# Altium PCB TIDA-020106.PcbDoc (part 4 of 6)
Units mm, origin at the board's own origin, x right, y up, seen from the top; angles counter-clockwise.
Board outline 158.53 x 83.25 mm, 6 copper layers (Top Layer, GND, Power, Sig4, GND (Mid4), Bottom Layer), stack 1.59 mm thick; 410 components, 255 nets, 1280 pads, 2405 vias.
Unrouted connection lines stored in the file: 294.
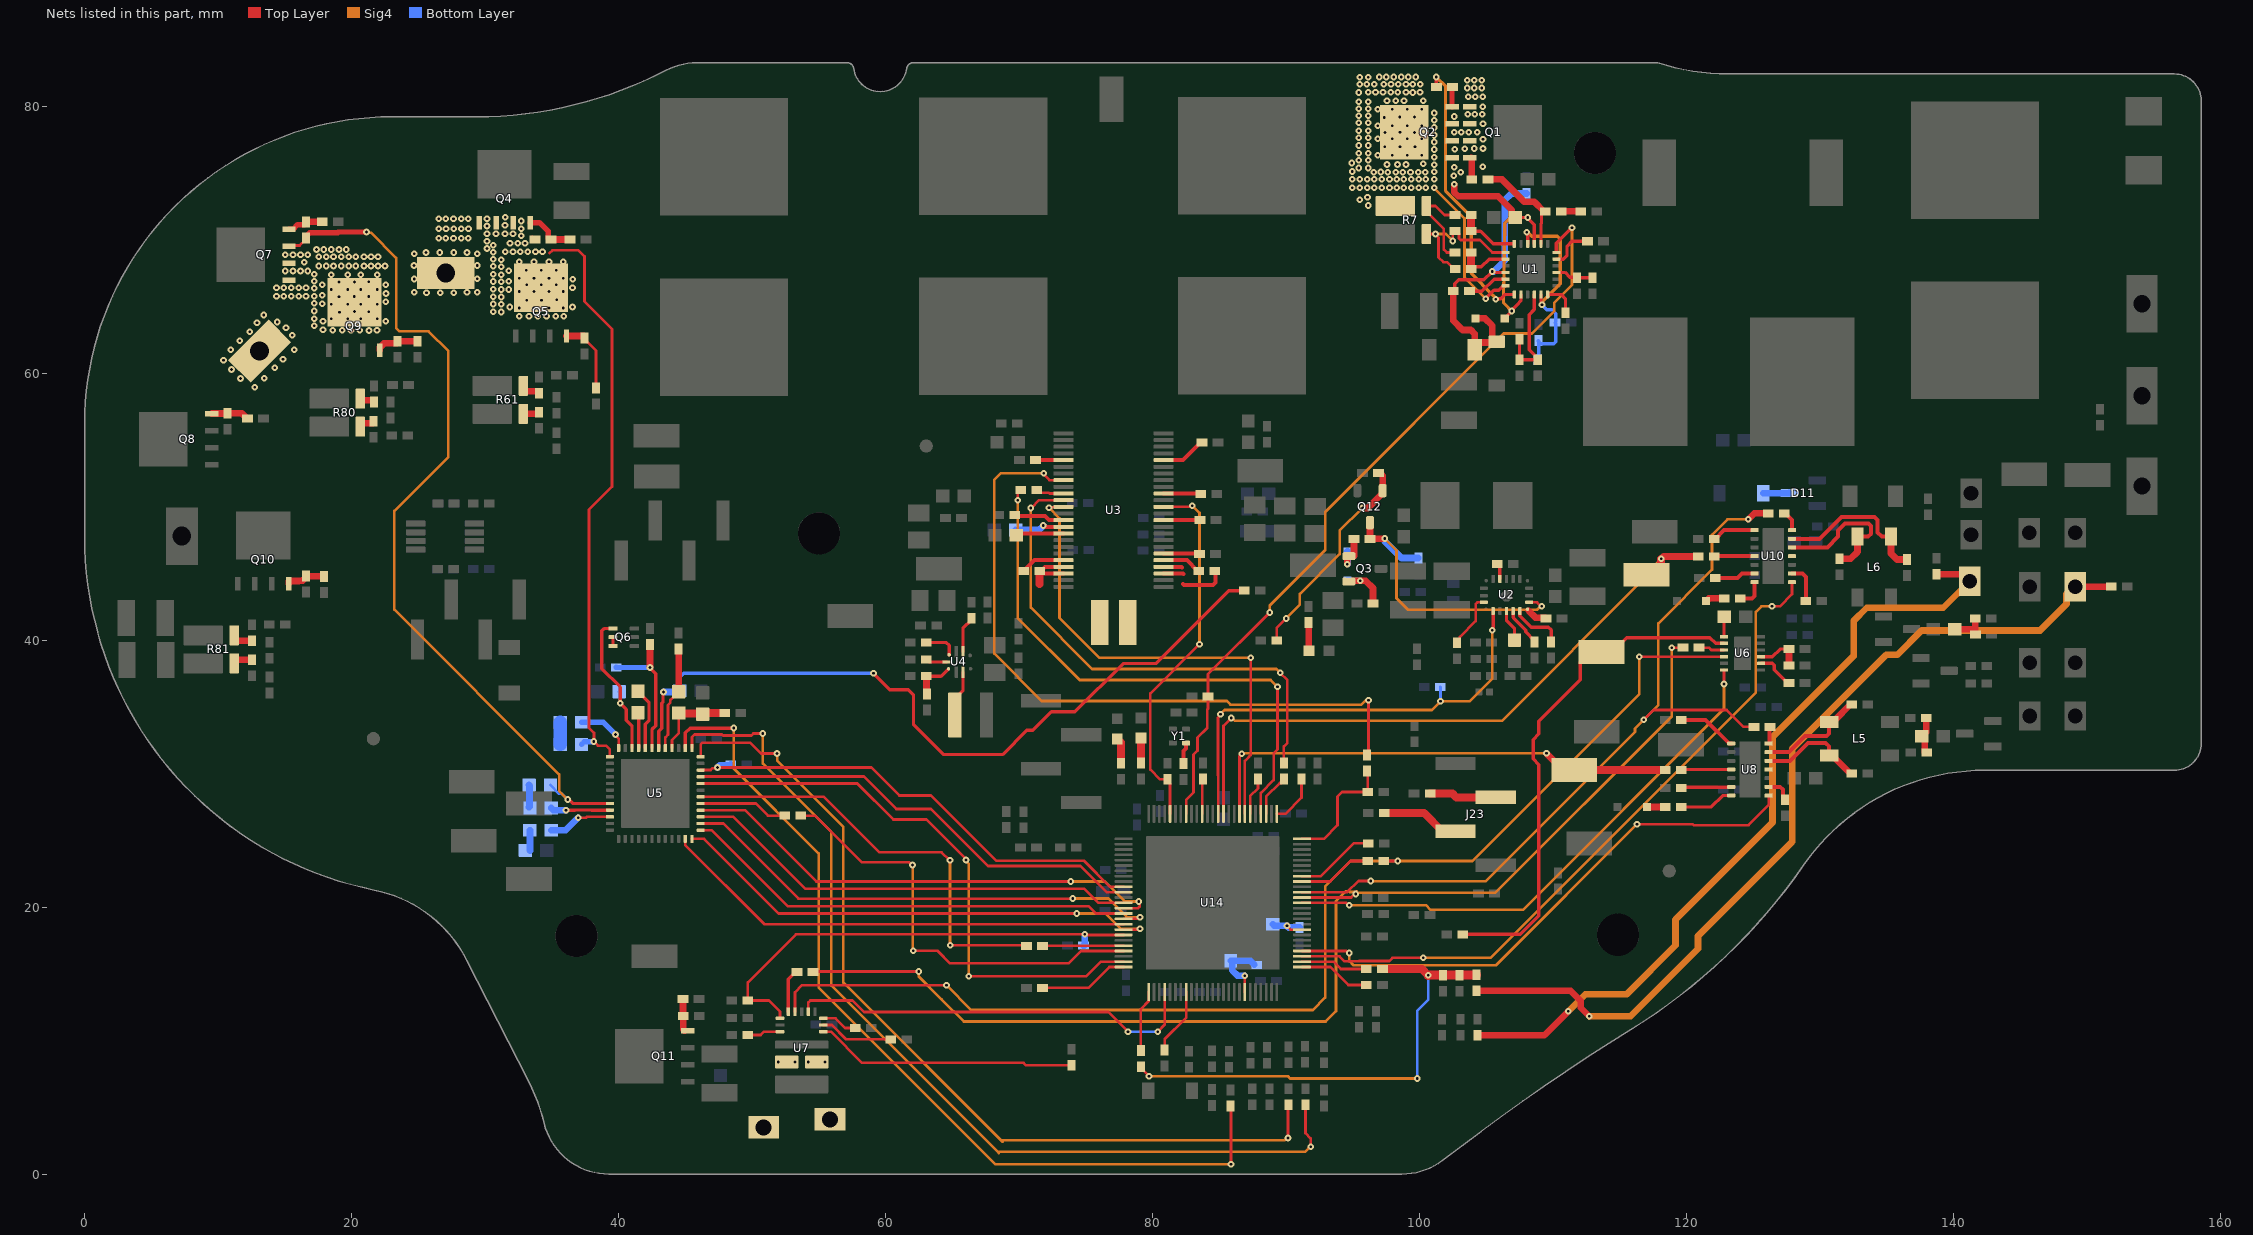
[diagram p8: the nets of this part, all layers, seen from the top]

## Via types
v1: diameter 0.5, hole 0.2, Top Layer to Bottom Layer, 2315 vias
v2: diameter 0.5, hole 0.2, Top Layer to Bottom Layer, tented both sides, 87 vias
v3: diameter 0.6, hole 0.2, Top Layer to Bottom Layer, 3 vias

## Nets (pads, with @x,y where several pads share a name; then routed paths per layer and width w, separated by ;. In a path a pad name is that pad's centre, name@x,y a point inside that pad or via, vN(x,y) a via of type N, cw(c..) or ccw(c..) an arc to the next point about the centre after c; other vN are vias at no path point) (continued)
nCS_DRV3263: U5.20 U14.99 | length 43.2
  Top Layer w0.2: U5.20@46.143,29.265 57.87,29.265 60.57,26.565 63.053,26.565 66.013,23.605 v1(66.013,23.532) ; v1(66.23,14.811) 75.013,14.811 76.119,15.917 U14.99@77.827,15.917
  Sig4 w0.2: v1(66.013,23.532) 66.013,23.451 66.23,23.234 v1(66.23,14.811)
NetC7_2: C7.2 D2.2 Q1.1 Q1.2 Q1.3 Q2.1 Q2.2 Q2.3 U1.2 U1.15 | length 20.2
  Top Layer w0.25: D2.2@106.371,64.098 106.892,64.62 v1(106.892,64.648) 106.892,64.716 107.293,65.117 107.293,65.123 107.586,65.416 U1.2@107.586,65.889 ; C7.2@107.157,71.658 v1(108.094,71.658) ; v1@108.097,71.61 108.586,71.121 U1.15@108.586,69.689
  Top Layer w0.5: v1(102.591,74.135) 102.591,73.536 102.884,73.243 105.863,73.243 106.903,72.202 106.903,71.883 107.128,71.658 C7.2@107.153,71.658 C7.2@107.157,71.658
  Sig4 w0.25: v1(106.892,64.648) 106.345,65.214 106.275,65.287 106.275,65.39 106.38,71.227 106.811,71.658 v1(108.094,71.658)
  other v1: 102.559,74.785 103.072,75.036 102.591,75.412 104.711,75.464 102.625,76.78 103.367,76.799 104.091,76.819 104.741,76.819 104.739,77.521 102.592,78.041 103.112,78.041 103.67,78.041 104.316,78.041 104.739,78.676 102.591,79.219 103.601,79.383 104.122,79.383 104.679,79.383 104.711,79.959 103.633,80.696 104.154,80.696 104.711,80.696 103.562,81.355 104.083,81.355 104.64,81.355 103.562,81.942 104.083,81.942 104.64,81.942
NetC11_1: C11.1 U1.23 | length 3.1
  Top Layer w0.2: C11.1@103.723,66.135 C11.1@103.823,66.135
  Top Layer w0.25: C11.1@103.823,66.135 104.663,66.135 105.568,67.039 U1.23@106.436,67.039
NetC11_2: C11.2 C12.2 D2.1 D10.1 R153.2 U1.22 | length 22.4
  Top Layer w0.25: C11.2@102.523,66.135 102.634,66.246 102.634,66.685 102.931,66.981 104.796,66.981 105.422,67.608 v1(105.422,67.614) 105.49,67.614 105.565,67.539 U1.22@106.436,67.539
  Top Layer w0.5: C11.2@102.523,66.135 102.523,63.925 103.213,63.235 103.829,63.235 104.122,62.942 C12.2@104.122,61.991 ; C12.2@104.122,61.741 C12.2@104.122,61.991 ; D2.1@104.171,64.098 104.894,64.098 105.435,63.558 105.435,62.558 D10.1@105.642,62.351 ; D10.1@105.704,62.291 104.422,62.291 C12.2@104.122,61.991
  Bottom Layer w0.5: v1(105.422,67.614) 105.551,67.614 106.371,68.434 106.371,72.963 106.866,73.459 R153.2@108.013,73.459
NetC13_1: C13.1 R10.1 U1.18 | length 4.8
  Top Layer w0.25: C13.1@103.849,70.633 104.558,70.633 105.501,69.689 U1.18@107.086,69.689
  Top Layer w0.6: C13.1@103.849,70.633 R10.1@103.849,71.845
NetC13_2: C13.2 C14.2 R7.3 U1.19 | length 11.1
  Top Layer w0.2: R7.3@100.462,70.413 100.464,70.415 v1(101.187,70.415) 101.187,70.368 101.407,70.148 101.407,68.669 101.767,68.309 102.04,68.309 102.56,67.789 C14.2@102.66,67.789 ; v1(102.487,69.895) 102.487,70.433 102.687,70.633 102.749,70.633 102.949,70.433 102.949,70.086 103.066,69.969 104.512,69.969 105.443,69.039 U1.19@106.436,69.039
  Sig4 w0.2: v1(101.187,70.415) 101.967,70.415 v1(102.487,69.895)
NetC14_1: C14.1 R11.1 U1.20 | length 4.1
  Top Layer w0.25: C14.1@103.849,67.789 C14.1@103.86,67.789 104.035,67.964 104.624,67.964 105.199,68.539 U1.20@106.436,68.539
  Top Layer w0.6: C14.1@103.849,67.789 R11.1@103.849,69.039
NetC15_1: C15.1 R12.1 R14.2 U1.4 | length 8.2
  Top Layer w0.25: R12.1@107.48,62.536 R14.2@107.48,61.004 108.292,61.004 C15.1@108.842,61.004 108.842,61.104 108.205,61.741 108.205,64.384 108.586,64.765 108.586,65.364 U1.4@108.586,65.889
NetC18_1: C18.1 R16.1 | length 1.5
  Top Layer w0.5: R16.1@110.596,72.122 C18.1@112.056,72.122
NetC19_1: C19.1 R21.2 U1.9 | length 2.9
  Top Layer w0.25: U1.9@110.236,67.539 110.886,67.539 111.251,67.174 111.736,67.174 R21.2@111.771,67.139 112.943,67.139 C19.1@112.947,67.135
NetC20_1: C20.1 U2.15 | length 1.2
  Top Layer w0.25: C20.1@105.815,45.711 105.827,45.711 106.002,45.536 U2.15@106.002,44.581
NetC29_2: C29.2 U2.4 | length 2.4
  Top Layer w0.25: U2.4@106.502,42.181 106.502,41.463 107.102,40.863 C29.2@107.102,40.002
NetC38_1: C38.1 L3.2 U3.3 U3.4 | length 6
  Top Layer w0.3: U3.3@80.824,44.985 81.802,44.985 82.282,44.985 82.316,44.952 ; U3.4@80.824,45.485 82.158,45.485 82.196,45.447 ; 82.274,44.203 82.356,44.121 84.525,44.121 84.702,44.298 C38.1@84.702,44.895
NetC38_2: C38.2 U3.5 | length 3
  Top Layer w0.3: U3.5@80.824,45.985 82.564,45.985 83.358,45.191 C38.2@83.458,45.191
NetC39_1: C39.1 L3.1 U3.45 U3.46 | length 4.7
  Top Layer w0.3: C39.1@71.536,45.191 C39.1@71.636,45.191 ; U3.46@73.324,44.985 71.841,44.985 C39.1@71.636,45.191 ; U3.45@73.324,45.485 71.931,45.485 C39.1@71.636,45.191
  Top Layer w0.6: 71.536,44.206 C39.1@71.536,45.191
NetC39_2: C39.2 U3.44 | length 3.4
  Top Layer w0.3: C39.2@70.336,45.191 70.436,45.191 70.586,45.341 70.586,45.441 71.131,45.985 U3.44@73.324,45.985
NetC53_2: C53.2 U3.39 | length 3.8
  Top Layer w0.3: v1(71.8,48.584) 71.854,48.584 71.953,48.485 U3.39@73.324,48.485
  Bottom Layer w0.5: C53.2@69.743,48.243 71.488,48.243 71.8,48.554 v1(71.8,48.584)
NetC54_2: C54.2 U3.40 | length 3.3
  Top Layer w0.3: C54.2@70.03,47.956 70.058,47.984 71.882,47.984 71.883,47.985 72.08,47.985 U3.40@73.324,47.985
NetC59_2: C59.2 U4.8 | length 1.7
  Top Layer w0.25: C59.2@62.957,38.549 63.057,38.549 63.241,38.365 U4.8@64.586,38.365
NetC62_1: C62.1 R51.1 U5.30 | length 57.9
  Top Layer w0.25: U5.30@42.993,31.915 42.993,33.168 43.218,33.393 43.218,35.263 43.32,35.365 43.32,36.076 v1(43.36,36.115) ; v1(59.085,37.517) 60.311,36.291 61.692,36.291 62.08,35.903 62.08,33.707 64.358,31.428 68.753,31.428 70.561,33.236 71.021,33.236 72.414,34.63 74.169,34.63 77.783,38.244 80.246,38.244 85.707,43.706 R51.1@86.852,43.706
  Bottom Layer w0.25: C62.1@44.569,36.218 44.569,37.202 44.884,37.517 v1(59.085,37.517)
  Bottom Layer w0.5: v1(43.36,36.115) 44.466,36.115 C62.1@44.569,36.218
NetC63_1: C63.1 R53.2 U5.29 | length 7.8
  Top Layer w0.2: U5.29@43.493,31.915 43.493,32.714 43.694,32.915 43.694,35.138 43.874,35.318 43.874,35.523 C63.1@44.494,36.143
  Top Layer w0.5: C63.1@44.494,36.143 R53.2@44.494,39.338
NetC63_2: C63.2 C64.2 R54.2 U5.28 | length 6.3
  Top Layer w0.2: U5.28@43.993,31.915 43.993,32.515 44.494,33.016 C63.2@44.494,34.543
  Top Layer w0.6: C63.2@44.494,34.543 44.539,34.498 46.248,34.498 C64.2@46.293,34.453 46.393,34.553 R54.2@47.888,34.553
NetC65_1: C65.1 U5.33 | length 2.7
  Top Layer w0.25: C65.1@41.443,34.57 41.493,34.52 U5.33@41.493,31.915
NetC65_2: C65.2 U5.32 | length 4.7
  Top Layer w0.25: C65.2@41.443,36.17 42.268,35.345 42.268,33.965 41.993,33.69 U5.32@41.993,31.915
NetC67_1: C67.1 Q6.4 U5.34 | length 11.5
  Top Layer w0.25: Q6.4@39.575,40.866 38.9,40.866 38.741,40.708 38.741,37.857 40.108,36.49 v1(40.108,35.268) 40.568,34.808 40.568,34.005 40.993,33.58 U5.34@40.993,31.915
  Bottom Layer w0.25: C67.1@40.033,36.143 40.108,36.068 v1(40.108,35.268)
NetC69_2: C69.2 R64.2 | length 1.7
  Bottom Layer w1: C69.2@35.619,32.186 R64.2@35.619,33.839
NetC72_2: C72.2 R65.2 | length 1.8
  Bottom Layer w0.2: R65.2@33.288,27.491 R65.2@33.352,27.427
  Bottom Layer w0.5: R65.2@33.288,27.491 33.32,27.523 33.32,29.113 C72.2@33.288,29.145
NetC77_2: C77.2 R68.2 | length 1.6
  Bottom Layer w0.5: R68.2@33.338,25.765 33.355,25.748 33.355,24.242 C77.2@33.372,24.225
NetC93_2: C93.2 R88.1 U6.3 | length 3.6
  Top Layer w0.25: U6.3@125.571,38.759 126.421,38.759 126.995,39.333 C93.2@127.655,39.333
  Top Layer w0.5: R88.1@127.659,38.105 C93.2@127.659,39.337
NetC95_1: C95.1 U6.7 | length 1.5
  Top Layer w0.25: U6.7@122.791,40.259 122.791,41.724 C95.1@122.816,41.749
NetC104_2: C104.2 R100.1 R103.2 | length 2.9
  Top Layer w0.5: R100.1@137.947,34.18 137.947,33.098 137.643,32.794 137.826,32.61 137.826,31.615 137.876,31.565 R103.2@137.976,31.565
NetC108_2: C108.2 R110.1 R113.2 | length 2.8
  Top Layer w0.5: C108.2@140.064,40.817 141.452,40.817 141.621,40.986 ; R110.1@141.618,41.634 141.621,41.63 141.621,40.986 ; R113.2@141.625,40.436 141.621,40.44 141.621,40.986
NetC116_1: C116.1 L7.2 U14.19 | length 5
  Top Layer w0.2: U14.19@86.902,13.642 v1(86.902,14.867)
  Bottom Layer w0.5: v1(86.902,14.867) 86.356,14.867 85.957,15.266 85.957,15.876 C116.1@85.843,15.989 87.309,15.989 L7.2@87.618,15.681
NetC117_1: C117.1 L8.2 U14.33 | length 3.4
  Top Layer w0.2: v1(90.057,18.595) 90.057,18.573 90.313,18.317 U14.33@91.177,18.317
  Bottom Layer w0.5: C117.1@88.989,18.723 89.116,18.595 v1(90.057,18.595) 90.18,18.473 L8.2@91.003,18.473
NetD3_1: D3.1 D11.3 | length 2
  Bottom Layer w0.5: D3.1@125.729,50.999 125.737,51.007 127.674,51.007 D11.3@127.681,51.014
NetD4_1: D4.1 R24.1 | length 2.1
  Top Layer w0.5: R24.1@91.665,41.317 91.684,41.298 91.684,39.221 D4.1@91.703,39.202
NetD6_2: D6.2 R102.2 | length 1.4
  Top Layer w0.5: D6.2@117.016,27.5 R102.2@118.393,27.5
NetD7_2: D7.2 R112.2 | length 1.4
  Top Layer w0.5: D7.2@121.454,42.922 121.66,43.127 R112.2@122.803,43.127
NetD8_2: D8.2 R151.1 | length 1.9
  Top Layer w0.6: D8.2@77.348,32.6 77.631,32.317 R151.1@77.631,30.773
NetD9_2: D9.2 R152.1 | length 1.9
  Top Layer w0.6: R152.1@79.123,30.793 D9.2@79.123,32.668
NetD13_1: D13.1 Q3.1 R28.1 | length 3
  Top Layer w0.5: v1(94.584,45.677) 94.584,46.241 94.634,46.291 Q3.1@94.699,46.291 ; Q3.1@95.026,46.255 95.076,46.305 R28.1@95.076,47.591
  Bottom Layer w0.5: v1(94.584,45.677) 94.589,45.681 D13.1@94.589,46.649
NetD13_2: D13.2 Q3.2 R23.2 | length 4
  Top Layer w0.5: Q3.2@94.875,44.366 94.949,44.441 95.53,44.441 v1(95.538,44.449) 95.949,44.449 96.5,43.898 R23.2@96.5,42.73
  Bottom Layer w0.5: D13.2@94.589,44.449 v1(95.538,44.449)
NetJ23_2: J23.2 R138.2 | length 5.9
  Top Layer w0.2: J23.2@101.927,25.68 J23.2@102.694,25.68
  Top Layer w0.6: R138.2@97.35,27.039 100.335,27.039 101.694,25.68 J23.2@101.927,25.68
NetJ23_3: J23.3 R139.2 | length 5
  Top Layer w0.6: R139.2@100.779,28.513 102.446,28.513 102.739,28.22 J23.3@105.694,28.22
NetL4_1: L4.1 U4.2 | length 3.5
  Top Layer w0.25: L4.1@65.176,34.394 65.176,35.604 65.786,36.214 U4.2@65.786,37.603
NetL5_3: L5.3 R98.2 U8.13 | length 8.2
  Top Layer w0.3: U8.13@126.136,31.608 127.677,31.608 128.877,32.808 130.472,32.808 130.676,33.012 L5.3@130.676,33.865
  Top Layer w0.5: L5.3@130.676,33.865 130.876,34.065 131.147,34.065 132.251,35.17 R98.2@132.351,35.17
NetL5_4: L5.4 R105.2 U8.12 | length 8.1
  Top Layer w0.3: U8.12@126.136,30.958 127.734,30.958 129.084,32.308 130.408,32.308 130.676,32.04 L5.4@130.676,31.365
  Top Layer w0.5: L5.4@130.676,31.365 130.901,31.365 132.201,30.065 132.201,30.047 132.251,29.997 R105.2@132.351,29.997
NetL6_3: L6.3 R109.2 U10.13 | length 11.9
  Top Layer w0.3: U10.13@127.889,47.59 129.959,47.59 131.598,49.228 134.051,49.228 134.3,48.98 134.3,48.071 134.627,47.743 L6.3@135.301,47.743
  Top Layer w0.5: L6.3@135.301,47.743 135.301,46.49 135.751,46.04 R109.2@136.492,46.04
NetL6_4: L6.4 R115.2 U10.12 | length 11.4
  Top Layer w0.3: U10.12@127.889,46.94 130.54,46.94 131.343,47.743 131.343,48.217 131.854,48.728 133.624,48.728 133.8,48.553 133.8,47.967 133.576,47.743 L6.4@132.801,47.743
  Top Layer w0.5: R115.2@131.455,46.092 132.275,46.092 132.793,46.611 132.793,47.736 L6.4@132.801,47.743
NetQ1_4: Q1.4 R9.2 | length 1.7
  Top Layer w0.5: Q1.4@103.849,76.136 103.865,76.136 103.91,76.091 R9.2@103.91,74.515
NetQ2_4: Q2.4 R8.2 | length 1.4
  Top Layer w0.4: R8.2@102.422,81.3 102.422,79.951 102.427,79.946 Q2.4@102.451,79.946
NetQ2_5: Q2.5 R7.2 U1.24 | length 11.8
  Top Layer w0.25: v1(104.95,65.566) 104.95,65.592 105.562,66.205 105.927,66.205 106.261,66.539 U1.24@106.436,66.539
  Sig4 w0.2: v1(101.078,73.875) 103.359,71.594 103.359,67.157 v1(104.95,65.566)
  other v1: 96.135,72.552 95.508,72.98 96.091,73.166 94.956,73.875 95.508,73.875 96.073,73.875 96.594,73.875 97.151,73.875 97.734,73.875 98.291,73.875 98.811,73.875 99.376,73.875 99.928,73.875 100.463,73.875 94.956,74.515 95.508,74.515 96.073,74.515 96.594,74.515 97.151,74.515 97.734,74.515 98.291,74.515 98.811,74.515 99.376,74.515 99.928,74.515 100.463,74.515 101.078,74.515 96.549,75.055 97.079,75.058 97.602,75.055 98.206,75.055 98.737,75.055 99.312,75.055 99.881,75.055 100.421,75.055 94.956,75.096 101.078,75.091 95.44,75.359 96.14,75.359 101.078,75.612 97.556,75.621 98.336,75.621 98.967,75.621 100.275,75.687 94.907,75.738 95.44,75.938 96.14,75.938 101.078,76.169 96.861,76.314 97.939,76.314 99.056,76.314 100.161,76.314 95.44,76.478 96.14,76.478 101.078,76.753 97.385,76.954 98.529,76.954 99.642,76.954 95.44,77.047 96.14,77.047 101.078,77.31 96.861,77.551 97.939,77.551 99.056,77.551 100.161,77.551 95.44,77.622 96.14,77.622 101.078,77.83 97.403,78.022 99.608,78.022 98.529,78.041 95.44,78.153 96.14,78.153 101.078,78.395 96.861,78.535 97.939,78.535 99.056,78.535 100.161,78.535 95.44,78.757 96.14,78.757 101.078,78.948 97.35,79.15 98.503,79.188 99.608,79.188 95.442,79.28 96.142,79.28 101.078,79.482 96.861,79.771 97.939,79.771 99.056,79.771 100.161,79.771 95.44,79.809 96.14,79.809 95.44,80.336 96.14,80.336 97.556,80.397 98.206,80.406 98.825,80.397 100.275,80.397 95.442,81.024 96.148,81.027 96.688,81.027 97.256,81.027 97.832,81.027 98.363,81.027 98.967,81.027 99.49,81.024 100.019,81.027 95.508,81.626 96.029,81.626 96.586,81.626 97.316,81.626 97.85,81.626 98.403,81.626 98.967,81.626 99.488,81.626 100.045,81.626 95.508,82.158 96.148,82.158 96.963,82.181 97.498,82.181 98.05,82.181 98.615,82.181 99.135,82.181 99.693,82.181
NetQ4_4: Q4.4 R50.1 R52.2 | length 3.8
  Top Layer w0.4: Q4.4@33.362,71.273 34.074,71.273 34.73,70.617 34.73,70.111 34.83,70.011 R52.2@34.93,70.011
  Top Layer w0.5: R52.2@34.93,70.011 R50.1@36.356,70.011
NetQ5_4: Q5.4 R55.1 R56.2 | length 5.6
  Top Layer w0.2: R56.2@37.441,62.627 37.441,62.527 37.641,62.327 37.665,62.327 38.299,61.694 R55.1@38.299,58.884
  Top Layer w0.5: Q5.4@36.092,62.777 37.391,62.777 37.441,62.727 R56.2@37.441,62.627
NetQ6_5: Q6.5 Q6.6 | length 0.7
  Top Layer w0.2: Q6.6@39.575,39.566 Q6.5@39.575,40.216
NetQ7_4: Q7.4 R66.1 R69.2 | length 2.8
  Top Layer w0.2: R66.1@17.776,71.317 R66.1@17.797,71.338
  Top Layer w0.4: Q7.4@15.308,70.763 15.603,70.763 15.956,71.117 16.466,71.117 16.566,71.217 R69.2@16.566,71.317
  Top Layer w0.5: R69.2@16.566,71.317 16.576,71.327 17.766,71.327 R66.1@17.776,71.317
NetQ8_4: Q8.4 R67.1 R70.2 | length 2.9
  Top Layer w0.5: Q8.4@9.511,56.952 9.535,56.976 10.676,56.976 R70.2@10.7,57 11.75,57 12.05,56.7 12.05,56.644 12.1,56.594 R67.1@12.2,56.594
NetQ9_4: Q9.4 R72.1 R74.2 | length 3.3
  Top Layer w0.2: R72.1@24.941,62.38 R72.1@24.942,62.381
  Top Layer w0.5: Q9.4@22.109,61.713 22.109,61.918 22.421,62.23 23.383,62.23 23.433,62.28 R74.2@23.433,62.38 ; R74.2@23.433,62.38 R72.1@24.941,62.381
NetQ10_4: Q10.4 R73.1 R75.2 | length 3.1
  Top Layer w0.5: Q10.4@15.286,44.226 15.286,44.386 15.331,44.431 16.053,44.431 16.08,44.458 16.316,44.458 16.566,44.708 R75.2@16.566,44.808 16.585,44.788 17.92,44.788 R73.1@17.939,44.769
NetQ11_4: Q11.4 R85.2 R87.2 | length 2.8
  Top Layer w0.2: R87.2@44.791,11.884 R87.2@44.826,11.849 ; R85.2@44.791,13.122 R85.2@44.791,13.222 ; Q11.4@44.931,10.735 Q11.4@45.163,10.735
  Top Layer w0.5: R87.2@44.791,11.884 44.803,11.884 44.818,11.899 R85.2@44.818,13.122 ; R87.2@44.826,11.849 44.826,10.866 44.931,10.761 Q11.4@44.931,10.735
NetQ12_1: Q12.1 R154.1 R155.1 | length 16.3
  Top Layer w0.2: R154.1@89.303,39.955 89.303,40.93 v1(89.992,41.619)
  Top Layer w0.5: v1(95.711,49.901) 96.127,49.901 97.225,50.998 97.225,52.317 97.011,52.531 R155.1@96.911,52.531
  Sig4 w0.2: v1(89.992,41.619) 91.027,42.654 91.027,43.471 94.007,46.451 94.007,48.196 v1(95.711,49.901)
NetQ12_3: Q12.3 R27.2 R28.2 U2.8 | length 22.8
  Top Layer w0.2: U2.8@108.202,42.831 108.802,42.831 109.106,42.527 v1(109.136,42.527)
  Top Layer w0.5: R28.2@96.276,47.591 Q12.3@96.275,48.798 ; R28.2@96.276,47.591 97.354,47.591 v1(97.376,47.614)
  Sig4 w0.2: v1(97.376,47.614) 98.262,46.727 98.262,43.137 99.125,42.274 108.802,42.274 109.055,42.527 v1(109.136,42.527)
  Bottom Layer w0.5: v1(97.376,47.614) 97.376,47.413 98.633,46.155 R27.2@99.9,46.155
NetR7_4: R7.4 R10.2 R11.2 | length 7.2
  Top Layer w0.2: R11.2@102.649,69.039 102.03,69.039 101.807,69.261 101.807,70.809 100.501,72.115 R7.4@100.501,72.515 101.181,72.515 101.851,71.845 R10.2@102.649,71.845
NetR8_1: R8.1 U1.1 | length 20.8
  Top Layer w0.25: v1(101.246,82.179) 101.246,81.428 R8.1@101.253,81.421 ; v1(105.703,65.532) 105.749,65.577 106.086,65.577 106.398,65.889 U1.1@107.086,65.889
  Sig4 w0.25: v1(101.246,82.179) 101.936,81.489 101.936,73.638 103.849,71.725 103.849,67.597 103.849,67.493 105.525,65.804 v1(105.703,65.532)
NetR9_1: R9.1 R16.2 U1.14 | length 7.7
  Top Layer w0.25: U1.14@109.086,69.689 109.086,71.183 109.121,71.218 109.121,71.947 R16.2@109.296,72.122
  Top Layer w0.5: R9.1@105.11,74.515 106.163,74.515 107.85,72.829 108.589,72.829 R16.2@109.296,72.122
NetR19_2: R19.2 U1.6 | length 2.5
  Top Layer w0.25: U1.6@109.586,65.889 110.596,65.889 110.919,65.566 R19.2@110.919,64.512
NetR20_2: R20.2 U1.11 | length 3.3
  Top Layer w0.25: U1.11@110.236,68.539 110.746,68.539 111.036,68.829 111.036,69.514 111.4,69.877 R20.2@112.571,69.877
NetR25_1: R25.1 U2.20 | length 4.1
  Top Layer w0.2: R25.1@102.802,39.807 103.002,40.007 103.002,40.235 104.195,41.428 104.195,42.714 104.312,42.831 U2.20@104.802,42.831
NetR26_2: R26.2 U2.7 | length 1.6
  Top Layer w0.2: U2.7@108.071,42.312 U2.7@108.171,42.312
  Top Layer w0.5: 108.171,42.189 108.677,41.684 109.411,41.684 R26.2@109.461,41.634
NetR29_2: R29.2 U2.6 | length 4
  Top Layer w0.25: U2.6@107.502,42.181 107.502,41.826 108.367,40.961 109.642,40.961 109.842,40.762 R29.2@109.842,39.859
NetR30_1: R30.1 U2.5 | length 3
  Top Layer w0.25: U2.5@107.002,42.181 107.002,41.689 107.939,40.752 107.939,40.618 108.598,39.959 R30.1@108.598,39.859
NetR36_2: R36.2 U3.6 | length 2.7
  Top Layer w0.3: U3.6@80.824,46.485 83.465,46.485 R36.2@83.509,46.441
NetR37_2: R37.2 U3.38 | length 3.8
  Top Layer w0.3: R37.2@69.652,49.363 69.717,49.298 71.935,49.298 72.247,48.985 U3.38@73.324,48.985
NetR38_2: R38.2 U3.11 | length 2.7
  Top Layer w0.3: U3.11@80.824,48.985 83.527,48.985 R38.2@83.546,49.005
NetR39_2: R39.2 U3.15 | length 2.8
  Top Layer w0.3: U3.15@80.824,50.985 83.543,50.985 R39.2@83.593,50.935
NetR40_2: R40.2 U3.20 | length 3.4
  Top Layer w0.3: U3.20@80.824,53.485 82.259,53.485 83.592,54.818 R40.2@83.692,54.818
NetR41_2: R41.2 U3.29 | length 2.1
  Top Layer w0.3: R41.2@71.217,53.485 U3.29@73.324,53.485
NetR42_2: R42.2 U3.34 | length 2.1
  Top Layer w0.2: R42.2@71.312,51.24 71.512,51.04 72.212,51.04 72.267,50.985 U3.34@73.324,50.985
NetR43_1: R43.1 U3.32 | length 52.6
  Top Layer w0.2: v1(71.841,52.505) 71.899,52.448 71.899,52.36 72.274,51.985 U3.32@73.324,51.985 ; R43.1@96.069,31.393 96.163,31.488 v1(96.163,35.502)
  Sig4 w0.2: v1(71.841,52.505) 68.632,52.505 68.143,52.016 68.143,38.985 71.686,35.442 85.557,35.442 85.83,35.169 95.623,35.169 95.899,35.445 96.106,35.445 v1(96.163,35.502)
NetR45_1: R45.1 U4.5 | length 2.8
  Top Layer w0.25: U4.5@65.786,39.128 65.786,40.883 66.439,41.536 R45.1@66.439,41.636
NetR46_1: R46.1 R48.1 U4.9 | length 3.2
  Top Layer w0.25: R48.1@63.042,37.294 64.146,37.294 U4.9@64.707,37.856
  Top Layer w0.5: R48.1@63.042,37.294 63.06,37.277 63.06,35.977 R46.1@63.077,35.959
NetR49_2: R49.2 U4.7 | length 2.5
  Top Layer w0.25: R49.2@62.992,39.817 64.534,39.817 64.748,39.603 U4.7@64.748,38.903
NetR57_2: R57.2 R58.1 U5.31 | length 10.6
  Top Layer w0.25: v1(42.347,37.949) 42.347,37.906 42.768,37.486 42.768,33.58 42.493,33.305 U5.31@42.493,31.915
  Top Layer w0.5: R57.2@42.34,39.666 42.34,37.956 v1(42.347,37.949)
  Bottom Layer w0.4: R58.1@39.812,37.959 39.817,37.954 42.342,37.954 v1(42.347,37.949)
NetR59_2: R59.2 U5.17 | length 6.7
  Top Layer w0.2: U5.17@46.143,27.765 50.274,27.765 51.184,26.855 R59.2@52.435,26.855
NetR60_2: R60.2 R61.4 | length 1.7
  Top Layer w0.3: R61.4@32.911,59.052 R61.4@32.911,59.057
  Top Layer w0.5: R61.4@32.863,59.052 32.863,58.752 32.963,58.652 33.999,58.652 34.049,58.602 R60.2@34.049,58.502
NetR61_3: R61.3 R63.2 | length 1.3
  Top Layer w0.5: R61.3@32.863,56.952 33.985,56.952 34.035,57.002 R63.2@34.035,57.078
NetR64_1: R64.1 U5.36 | length 4
  Top Layer w0.2: v1(39.768,32.924) 39.768,32.843 39.993,32.617 U5.36@39.993,31.915
  Bottom Layer w0.4: R64.1@37.219,33.839 38.853,33.839 v1(39.768,32.924)
NetR65_1: R65.1 U5.45 | length 4.5
  Top Layer w0.25: v1(36.05,27.265) 36.724,27.265 36.734,27.275 37.985,27.275 37.995,27.265 U5.45@39.343,27.265
  Bottom Layer w0.5: R65.1@34.952,27.427 35.114,27.265 v1(36.05,27.265)
NetR68_1: R68.1 U5.46 | length 4.8
  Top Layer w0.2: v1(36.972,26.7) 37.557,26.7 37.622,26.765 U5.46@39.343,26.765
  Bottom Layer w0.5: R68.1@34.938,25.765 36.038,25.765 v1(36.972,26.7)
NetR71_2: R71.2 U5.26 | length 67.7
  Top Layer w0.2: R71.2@85.843,5.102 85.862,5.083 v1(85.862,0.75)
  Top Layer w0.25: U5.26@44.993,31.915 44.993,33.054 45.349,33.411 v1(48.618,33.411)
  Sig4 w0.2: v1(48.618,33.411) 48.618,30.39 54.979,24.029 54.979,13.972 68.201,0.75 v1(85.862,0.75)
NetR76_2: R76.2 U5.25 | length 71.9
  Top Layer w0.2: U5.25@45.493,31.915 45.493,32.732 45.696,32.935 47.743,32.935 47.817,32.861 49.941,32.861 50.085,33.004 v1(50.799,33.004) ; R76.2@91.445,5.191 91.445,3.065 91.827,2.683 v1(91.827,2.045)
  Sig4 w0.2: v1(50.799,33.004) 50.799,30.759 55.929,25.629 55.929,14.117 68.472,1.574 ; 68.472,1.674 91.42,1.674 91.791,2.045 v1(91.827,2.045)
NetR77_2: R77.2 U5.24 | length 67
  Top Layer w0.2: U5.24@46.143,31.265 46.143,32.165 46.293,32.315 49.844,32.315 50.654,31.504 v1(51.856,31.504) ; v1(90.14,2.7) 90.14,5.156 R77.2@90.175,5.191
  Sig4 w0.2: v1(51.856,31.504) 51.889,31.471 51.889,30.954 56.828,26.016 56.828,14.357 68.758,2.427 ; 68.758,2.527 89.885,2.527 90.059,2.7 v1(90.14,2.7)
NetR78_2: R78.2 R80.4 | length 1.3
  Top Layer w0.3: R80.4@20.483,58.053 20.483,58.038 R80.4@20.54,57.981
  Top Layer w0.5: R80.4@20.645,58.085 20.645,58.062 20.745,57.962 21.61,57.962 21.66,57.912 R78.2@21.66,57.838
NetR79_2: R79.2 R81.4 | length 1.7
  Top Layer w0.3: R81.4@11.26,40.36 R81.4@11.26,40.413
  Top Layer w0.5: R81.4@11.195,40.36 11.195,40.057 11.295,39.957 R79.2@12.522,39.957
NetR80_3: R80.3 R82.2 | length 1.3
  Top Layer w0.5: R80.3@20.645,55.985 20.645,56.148 20.745,56.248 21.579,56.248 21.629,56.298 R82.2@21.629,56.398
NetR81_3: R81.3 R83.2 | length 1.6
  Top Layer w0.5: R81.3@11.195,38.26 11.195,38.437 11.295,38.537 R83.2@12.534,38.537
NetR84_1: R84.1 TP16.1 U6.8 | length 38.6
  Top Layer w0.25: R84.1@103.227,17.963 107.542,17.963 108.928,19.35 108.928,30.681 108.505,31.104 108.505,32.553 108.928,32.976 108.928,33.929 112.028,37.029 112.028,38.345 112.792,39.109 TP16.1@113.617,39.109 114.443,39.109 115.521,40.187 121.738,40.187 122.166,39.759 U6.8@122.791,39.759
NetR86_1: R86.1 U6.2 | length 2.9
  Top Layer w0.25: U6.2@125.571,38.259 126.41,38.259 126.556,38.112 126.556,37.79 127.559,36.787 R86.1@127.659,36.787
NetR89_2: R89.2 U6.9 | length 1.9
  Top Layer w0.2: R89.2@120.916,39.433 121.664,39.433 121.838,39.259 U6.9@122.791,39.259
Netr90_2: R90.2 U7.8 | length 19.6
  Top Layer w0.2: U7.8@55.335,10.67 55.901,10.67 58.238,8.333 70.331,8.333 70.51,8.154 R90.2@73.919,8.154
NetR91_1: R91.1 U7.3 | length 2.5
  Top Layer w0.2: R91.1@49.669,10.425 50.635,10.425 50.88,10.67 U7.3@52.085,10.67
NetR93_2: R93.2 U7.9 | length 5.4
  Top Layer w0.2: U7.9@55.335,11.17 55.967,11.17 57.044,10.093 R93.2@60.29,10.093
NetR94_2: R94.2 U7.10 | length 2.7
  Top Layer w0.2: U7.10@55.335,11.67 56.239,11.67 56.962,10.947 R94.2@57.72,10.947
NetR96_2: R96.2 U7.15 | length 3.3
  Top Layer w0.25: U7.15@52.71,12.17 52.71,14.591 53.26,15.141 R96.2@53.36,15.141
NetR101_2: R101.2 U8.1 | length 4.5
  Top Layer w0.3: R101.2@119.593,34.029 121.416,34.029 123.186,32.258 U8.1@123.336,32.258
NetR102_1: R102.1 U8.7 | length 4.1
  Top Layer w0.25: R102.1@119.593,27.5 121.841,27.5 122.699,28.358 U8.7@123.336,28.358
NetR104_1: R104.1 U8.9 | length 2
  Top Layer w0.3: U8.9@126.136,29.008 127.006,29.008 127.206,28.808 127.206,28.189 R104.1@127.356,28.039
NetR106_2: R106.2 U8.14 | length 1.3
  Top Layer w0.3: U8.14@126.136,32.258 126.186,32.258 126.186,33.458 R106.2@126.237,33.508
NetR107_2: R107.2 U8.6 | length 3.8
  Top Layer w0.25: R107.2@119.593,28.908 119.668,28.983 123.311,28.983 U8.6@123.336,29.008
NetR108_2: R108.2 U8.4 | length 3.8
  Top Layer w0.25: R108.2@119.593,30.264 119.637,30.308 U8.4@123.336,30.308
NetR111_2: R111.2 U10.1 | length 3.4
  Top Layer w0.3: R111.2@122.054,47.591 122.154,47.591 122.803,48.24 U10.1@125.034,48.24 ; U10.1@125.084,48.24 U10.1@125.034,48.24 ; U10.1@125.089,48.24 U10.1@125.034,48.24
NetR112_1: R112.1 U10.7 | length 2.2
  Top Layer w0.3: R112.1@124.003,43.127 124.905,43.127 125.089,43.311 U10.7@125.089,44.34
NetR114_1: R114.1 U10.9 | length 2.9
  Top Layer w0.3: U10.9@127.884,44.99 U10.9@127.889,44.99 128.663,44.99 128.919,44.734 R114.1@128.919,42.941
NetR116_2: R116.2 U10.14 | length 1.6
  Top Layer w0.3: R116.2@127.302,49.501 127.402,49.501 127.889,49.014 U10.14@127.889,48.24
NetR117_2: R117.2 U10.6 | length 3.1
  Top Layer w0.3: R117.2@122.136,44.637 123.794,44.637 124.148,44.99 U10.6@125.089,44.99
NetR118_2: R118.2 U10.4 | length 3
  Top Layer w0.3: R118.2@122.073,46.264 122.099,46.29 U10.4@125.084,46.29
NetR128_1: R128.1 U14.26 | length 5.4
  Top Layer w0.2: U14.26@91.177,15.517 93.301,15.517 94.655,14.163 R128.1@96.008,14.163
NetR129_1: R129.1 U14.27 | length 5.1
  Top Layer w0.2: U14.27@91.177,15.917 93.542,15.917 94.092,15.367 R129.1@96.008,15.367
NetR133_2: R133.2 U14.42 | length 5.6
  Top Layer w0.2: U14.42@91.177,21.917 93.293,21.917 94.828,23.452 R133.2@96.115,23.452
NetR134_2: R134.2 U14.51 | length 3.7
  Top Layer w0.2: U14.51@89.302,26.992 89.937,26.992 91.144,28.199 R134.2@91.144,29.597
NetR135_2: R135.2 U14.43 | length 6
  Top Layer w0.2: U14.43@91.177,22.317 92.589,22.317 95.054,24.782 R135.2@96.15,24.782
NetR137_1: R137.1 Y1.3 | length 1.6
  Top Layer w0.3: R137.1@82.316,30.758 82.316,31.701 82.48,31.864 82.48,32.267 Y1.3@82.502,32.289
NetR140_1: R140.1 U14.53 | length 3.2
  Top Layer w0.2: U14.53@88.502,26.992 88.502,28.272 89.527,29.297 89.627,29.297 89.827,29.497 R140.1@89.827,29.597
NetR141_2: R141.2 U14.96 | length 6.1
  Top Layer w0.2: R141.2@71.749,16.988 71.878,17.117 U14.96@77.827,17.117
NetR142_1: R142.1 U14.56 | length 2.8
  Top Layer w0.2: U14.56@87.302,26.992 87.302,28.317 87.882,28.897 R142.1@87.882,29.597
NetR143_2: R143.2 U14.100 | length 6.7
  Top Layer w0.2: R143.2@71.749,13.958 75.197,13.958 76.756,15.517 U14.100@77.827,15.517
NetR144_1: R144.1 U14.1 | length 4.6
  Top Layer w0.2: R144.1@79.11,9.254 79.11,12.357 79.702,12.949 U14.1@79.702,13.642
NetR145_1: R145.1 U14.8 | length 5
  Top Layer w0.2: R145.1@80.902,9.295 80.902,10.105 82.502,11.705 U14.8@82.502,13.642
NetR146_1: R146.1 U14.65 | length 2.6
  Top Layer w0.2: U14.65@83.702,26.992 83.702,29.533 R146.1@83.771,29.602
NetU8_11: U8.11
NetU10_11: U10.11
nFAULT_CAN1: U8.8 U14.29 | length 41.5
  Top Layer w0.2: U14.29@91.177,16.717 94.522,16.717 94.672,16.567 v1(94.732,16.567) ; v1(116.277,26.217) 120.45,26.217 120.53,26.136 124.622,26.136 126.136,27.65 U8.8@126.136,28.358
  Sig4 w0.2: v1(94.732,16.567) 94.732,15.967 95.052,15.647 105.707,15.647 v1(116.277,26.217)
nFAULT_CAN2: U10.8 U14.28 | length 52.7
  Top Layer w0.2: U14.28@91.177,16.317 94.001,16.317 94.375,15.943 95.459,15.943 95.483,15.967 97.726,15.967 97.955,16.197 v1(100.254,16.197) ; v1(126.386,42.527) 126.973,42.527 127.889,43.442 U10.8@127.889,44.34
  Sig4 w0.2: v1(100.254,16.197) 105.297,16.197 125.181,36.081 125.181,42.122 125.586,42.527 v1(126.386,42.527)
nFAULT_EPB: C99.2 R92.2 U7.1 U14.94 | length 35.2
  Top Layer w0.2: U7.1@52.085,11.67 52.085,12.17 51.249,13.005 R92.2@49.669,13.005 49.669,14.362 53.27,17.963 v1(74.9,17.963) 74.946,17.917 U14.94@77.827,17.917
  Bottom Layer w0.5: C99.2@74.821,17.117 74.85,17.117 74.9,17.167 v1(74.9,17.963)
nFLT_DRV3263: R62.1 U5.22 U14.85 | length 36.9
  Top Layer w0.2: U5.22@46.143,30.265 46.885,30.265 47.026,30.406 47.258,30.406 47.336,30.485 v1@47.336,30.524 ; v1@47.299,30.562 v1@47.336,30.524 ; v1(47.396,30.464) v1@47.336,30.524 ; U14.85@77.827,21.517 76.799,21.517 74.834,23.482 68.272,23.482 63.389,28.365 61.024,28.365 58.925,30.464 47.472,30.464 47.394,30.542 47.336,30.599 v1@47.336,30.524
  Bottom Layer w0.5: v1(47.396,30.464) 47.564,30.632 48.354,30.632 R62.1@48.404,30.682
nFLT_LM74930: R15.1 U1.12 U14.68 | length 59.5
  Top Layer w0.2: U14.68@82.502,26.992 82.502,28.036 83.058,28.593 83.058,31.421 83.356,31.718 83.356,32.693 84.097,33.435 84.097,34.815 84.146,34.865 R15.1@84.146,35.77 84.146,37.449 v1(88.767,42.069)
  Top Layer w0.25: U1.12@110.236,69.039 110.236,69.729 v1(111.406,70.898)
  Sig4 w0.2: v1(88.767,42.069) 88.767,42.6 92.924,46.757 92.924,49.599 106.287,62.962 108.4,62.962 110.086,64.648 110.086,65.283 111.406,66.602 v1(111.406,70.898)
nSCS_EPB: U7.12 U14.4 | length 31.1
  Top Layer w0.2: U7.12@54.21,12.17 54.21,12.857 54.352,12.999 57.519,12.999 58.38,12.139 76.679,12.139 v1(78.148,10.67) ; v1(80.381,10.67) 80.902,11.191 U14.4@80.902,13.642
  Bottom Layer w0.2: v1(78.148,10.67) v1(80.381,10.67)
nSCS_PMIC: U3.36 U14.57 | length 37.1
  Top Layer w0.2: v1(72.227,49.918) 72.26,49.952 73.29,49.952 U3.36@73.324,49.985 ; U14.57@86.902,26.992 86.902,30.947 87.216,31.26 87.216,31.269 87.352,31.406 v1(87.352,38.671)
  Sig4 w0.2: v1(72.227,49.918) 73.024,49.12 73.024,41.665 76.019,38.671 v1(87.352,38.671)
nSCS_WSS: U6.12 U14.38 | length 41
  Top Layer w0.2: U14.38@91.177,20.317 94.481,20.317 94.651,20.148 v1(94.732,20.148) ; v1(122.791,36.718) U6.12@122.791,37.759
  Sig4 w0.2: v1(94.732,20.148) 100.474,20.148 100.825,19.797 107.729,19.797 122.791,34.859 v1(122.791,36.718)
nSLEEP_DRV3263: U5.21 U14.86 | length 35.3
  Top Layer w0.2: U5.21@46.143,29.765 46.166,29.789 58.367,29.789 60.801,27.355 63.398,27.355 67.671,23.082 74.586,23.082 76.551,21.117 U14.86@77.827,21.117
nSTB_CAN: R106.1 R116.1 U14.40 | length 61.1
  Top Layer w0.2: U14.40@91.177,21.117 94.57,21.117 95.412,21.96 v1(96.339,21.96) ; v1(116.778,34.029) 117.519,34.77 122.995,34.77 124.257,33.508 R106.1@125.037,33.508
  Top Layer w0.5: v1(124.61,49.043) 125.068,49.501 R116.1@126.102,49.501
  Sig4 w0.2: v1(96.339,21.96) 96.364,21.934 104.933,21.934 116.127,33.129 116.127,33.378 v1(116.778,34.029) 117.876,35.127 117.876,41.262 121.888,45.274 121.888,47.89 123.041,49.043 v1(124.61,49.043)
nXRS_DSP: C120.1 U3.13 U14.71 | length 27.9
  Top Layer w0.2: U3.13@80.824,49.985 82.82,49.985 82.893,50.059 v1(82.974,50.059) ; U14.71@81.302,26.992 81.302,29.265 81.1,29.467 C120.1@81.1,29.567 80.561,29.567 79.823,30.305 79.823,36.018 v1(83.502,39.698)
  Sig4 w0.2: v1(82.974,50.059) 83.502,49.531 v1(83.502,39.698)
OUTA_EPB: J5.1 U7.7
  other v2: 54.21,8.395 55.46,8.395
OUTB_EPB: J6.1 U7.5 | length 0.6
  Top Layer w0.2: v2(51.96,8.395) U7.5@52.585,8.395
  other v2: 53.21,8.395
OV: C17.1 R13.1 R17.2 U1.5 U1.16 | length 16.4
  Top Layer w0.25: v1(108.011,70.558) 108.011,70.49 108.086,70.415 U1.16@108.086,69.689 ; U1.5@109.086,65.889 109.086,65.254 109.161,65.179 v1(109.161,65.111)
  Sig4 w0.25: v1(108.011,70.558) 108.078,70.558 108.384,70.253 110.32,70.253 110.524,70.049 110.524,66.695 109.218,65.388 109.218,65.345 109.209,65.336 109.209,65.159 v1(109.161,65.111)
  Bottom Layer w0.25: C17.1@108.842,61.004 108.921,61.083 108.921,62.406 R13.1@108.886,62.441 108.886,62.371 109.061,62.196 110.048,62.196 110.197,62.345 110.197,63.719 R17.2@110.14,63.775 110.197,63.832 110.197,64.451 109.913,64.735 109.516,64.735 109.161,65.089 v1(109.161,65.111)
PEDAL_SENSOR_SENT: C2.1 R2.2 R4.2 R129.2 R144.2 | length 36.5
  Top Layer w0.2: R144.2@79.11,8.054 79.11,7.954 79.722,7.342 v1(79.722,7.334)
  Top Layer w0.6: R129.2@97.208,15.367 100.166,15.367 v1(100.63,14.903)
  Top Layer w0.7: v1(100.63,14.903) 100.646,14.919 104.24,14.919 R4.2@104.256,14.935
  Sig4 w0.2: v1(79.722,7.334) 90.115,7.334 90.286,7.163 v1(99.82,7.163)
  Bottom Layer w0.2: v1(99.82,7.163) 99.82,12.244 100.63,13.055 v1(100.63,14.903)
PFS: J12.1 R3.1 R5.2 | length 60.1
  Top Layer w0.5: R3.1@104.342,10.4 109.335,10.4 v1(111.138,12.203) ; R5.2@138.715,44.94 140.66,44.94 J12.1@141.2,44.4
  Sig4 w0.5: v1(111.138,12.203) 112.404,13.469 115.486,13.469 119.162,17.144 119.162,19.066 126.429,26.333 126.429,32.738 132.5,38.809 132.5,41.431 133.49,42.421 139.221,42.421 J12.1@141.2,44.4
PG_LM68645: R31.2 U2.2 U14.62 | length 35.2
  Top Layer w0.2: U14.62@84.902,26.992 84.902,29.883 84.897,29.888 84.897,34.191 85.075,34.368 v1(85.075,34.45)
  Top Layer w0.25: v1(105.422,40.728) 105.422,40.796 105.502,40.876 U2.2@105.502,42.181
  Sig4 w0.2: v1(85.075,34.45) 85.395,34.769 100.913,34.769 v1(101.555,35.412) 103.73,35.412 105.422,37.104 v1(105.422,40.728) v1@105.433,40.717
  Bottom Layer w0.2: R31.2@101.533,36.505 101.555,36.483 v1(101.555,35.412)
PMIC_DIAG_OUT: C55.1 R43.2 U14.50 | length 9
  Top Layer w0.2: U14.50@91.177,25.117 92.825,25.117 93.843,26.136 93.843,28.273 94.191,28.621 C55.1@96.104,28.621 96.108,28.625 R43.2@96.108,30.021
PTS: J14.1 R4.1 R6.1 | length 67
  Top Layer w0.5: R4.1@104.256,13.735 111.289,13.735 112.062,12.962 112.062,12.461 v1(112.695,11.828) ; J14.1@149,44 R6.1@151.8,44
  Sig4 w0.5: v1(112.695,11.828) 115.783,11.828 120.839,16.884 120.839,17.832 127.898,24.89 127.898,31.856 134.937,38.895 135.769,38.895 137.599,40.724 146.472,40.724 148.45,42.703 148.45,43.45 J14.1@149,44
PWMAH: U5.11 U14.92 | length 35.8
  Top Layer w0.2: U5.11@44.993,25.115 44.993,24.632 50.907,18.717 U14.92@77.827,18.717
PWMAL: U5.12 U14.93 | length 37.6
  Top Layer w0.2: U5.12@45.493,25.115 46.391,25.115 51.988,19.517 v1(74.301,19.517) ; U14.93@77.827,18.317 78.896,18.317 78.971,18.392 v1(79.052,18.392)
  Sig4 w0.2: v1(74.301,19.517) 76.474,19.517 77.599,18.392 v1(79.052,18.392)
PWMBH: U5.13 U14.90 | length 34.3
  Top Layer w0.2: U5.13@46.143,25.765 46.958,25.765 52.656,20.067 75.203,20.067 75.753,19.517 U14.90@77.827,19.517
PWMBL: U5.14 U14.91 | length 37.1
  Top Layer w0.2: U5.14@46.143,26.265 47.839,26.265 53.469,20.635 74.009,20.635 v1(74.014,20.641) ; U14.91@77.827,19.117 78.935,19.117 79.063,19.246 v1(79.043,19.246)
  Sig4 w0.2: v1(74.014,20.641) 76.683,20.641 78.079,19.246 v1(79.043,19.246)
PWMCH: U5.15 U14.88 | length 34.4
  Top Layer w0.2: U5.15@46.143,26.765 48.587,26.765 53.985,21.367 74.879,21.367 75.929,20.317 U14.88@77.827,20.317
PWMCL: U5.16 U14.89 | length 37.3
  Top Layer w0.2: U5.16@46.143,27.265 49.457,27.265 54.805,21.917 v1(73.868,21.917) ; U14.89@77.827,19.917 78.902,19.917 79.027,20.042 79.027,20.207 79.006,20.228 79.006,20.369 v1(78.949,20.426)
  Sig4 w0.2: v1(73.868,21.917) 76.431,21.917 77.921,20.426 v1(78.949,20.426)
RX_CAN1: R108.1 TP22.1 U14.58 | length 36.8
  Top Layer w0.2: U14.58@86.502,26.992 86.502,31.324 v1(86.666,31.488) ; TP22.1@111.582,30.264 TP22.1@111.926,30.264
  Top Layer w0.5: v1(109.503,31.518) 110.757,30.264 TP22.1@111.582,30.264
  Top Layer w0.6: TP22.1@111.926,30.264 R108.1@118.393,30.264
  Sig4 w0.2: v1(86.666,31.488) 86.704,31.527 109.494,31.527 v1(109.503,31.518)
RX_CAN2: R118.1 TP23.1 U14.61 | length 49.7
  Top Layer w0.2: U14.61@85.302,26.992 85.302,30.049 85.297,30.054 85.297,33.578 v1(85.887,34.168)
  Top Layer w0.5: v1(118.092,46.092) 118.264,46.264 R118.1@120.873,46.264
  Top Layer w0.6: TP23.1@116.995,44.895 117.503,44.895 118.092,45.484 v1(118.092,46.092)
  Sig4 w0.2: v1(85.887,34.168) 85.936,34.168 86.154,33.95 106.155,33.95 116.778,44.573 116.778,44.778 v1(118.092,46.092)
SDI_DRV3263: R141.1 U5.18 | length 32.8
  Top Layer w0.2: U5.18@46.143,28.265 55.372,28.265 59.533,24.103 64.185,24.103 64.769,23.519 v1(64.821,23.519) ; v1(64.825,17.133) 70.51,17.133 R141.1@70.549,17.094
  Sig4 w0.2: v1(64.821,23.519) 64.823,23.517 64.823,17.135 v1(64.825,17.133)
SDI_PMIC: R140.2 U3.35 | length 37.9
  Top Layer w0.2: v1(70.873,49.901) 70.912,49.901 71.497,50.485 U3.35@73.324,50.485 ; v1(89.551,37.552) 90.082,37.021 90.082,32.294 89.827,32.04 R140.2@89.827,30.797
  Sig4 w0.2: v1(70.873,49.901) 70.873,42.43 75.467,37.836 89.267,37.836 v1(89.551,37.552)
SDIEPB: R133.1 U6.10 U7.14 | length 90.6
  Top Layer w0.2: U7.14@53.21,12.17 53.21,13.619 53.743,14.152 v1(64.549,14.152) ; R133.1@97.315,23.452 v1(98.361,23.452) ; v1(116.449,38.759) U6.10@122.791,38.759
  Sig4 w0.2: v1(64.549,14.152) 66.405,12.297 91.992,12.297 92.923,13.227 92.923,21.547 94.828,23.452 v1(98.361,23.452) 103.95,23.452 116.455,35.957 116.455,38.752 v1(116.449,38.759)
SDO_DRV3263: R59.1 U14.97 | length 32.9
  Top Layer w0.2: R59.1@53.635,26.855 54.713,26.855 58.211,23.356 61.741,23.356 61.942,23.155 v1(62.008,23.155) ; v1(62.054,16.725) 63.899,16.725 64.832,15.792 73.702,15.792 74.627,16.717 U14.97@77.827,16.717
  Sig4 w0.2: v1(62.008,23.155) 62.031,23.132 62.031,16.748 v1(62.054,16.725)
SDO_PMIC: R42.1 U14.54 | length 41.3
  Top Layer w0.2: v1(69.882,50.485) 69.882,51.04 70.082,51.24 R42.1@70.112,51.24 ; U14.54@88.102,26.992 88.102,28.551 89.056,29.505 89.056,31.514 89.349,31.806 v1(89.349,36.505)
  Sig4 w0.2: v1(69.882,50.485) 69.882,41.672 74.537,37.017 88.836,37.017 v1(89.349,36.505)
SDOEPB: R89.1 R96.1 U14.39 | length 90.9
  Top Layer w0.2: R96.1@54.56,15.141 54.599,15.181 v1(62.467,15.181) ; U14.39@91.177,20.717 94.866,20.717 95.132,20.984 v1(95.214,20.984) ; v1(118.879,39.433) R89.1@119.716,39.433
  Sig4 w0.2: v1(62.467,15.181) 62.476,15.172 62.476,14.811 64.191,13.097 65.857,11.431 92.959,11.431 93.736,12.208 93.736,20.453 94.474,21.191 94.674,21.191 94.738,21.127 95.225,21.127 95.289,21.191 95.289,21.144 95.363,21.07 105.656,21.07 118.879,34.293 v1(118.879,39.433) ; v1(95.214,20.984) 95.225,20.995 v1@95.225,21.127
SHA: C69.1 J7.1 Q4.1 Q4.2 Q4.3 Q5.5 R52.1 U5.37 | length 44.3
  Top Layer w0.2: R52.1@33.531,70.21 R52.1@33.68,70.061 ; R52.1@33.63,70.011 R52.1@33.73,70.011 ; 34.822,68.996 35.025,69.2 36.982,69.2 37.434,68.748 37.434,65.361 39.493,63.302 39.493,51.492 37.777,49.776 37.777,33.43 38.153,33.054 38.153,32.416 v1(38.141,32.404) 38.452,32.093 39.045,32.093 39.343,31.795 U5.37@39.343,31.265
  Bottom Layer w0.4: C69.1@37.219,32.186 37.418,32.385 38.122,32.385 v1(38.141,32.404)
  other v1: 32.558,64.266 33.28,64.266 33.93,64.266 34.593,64.266 35.286,64.254 35.881,64.266 31.208,64.581 30.61,64.604 32.557,64.878 33.662,64.878 34.779,64.878 35.857,64.878 31.833,64.953 36.543,64.953 31.208,65.159 30.61,65.182 33.11,65.461 34.214,65.461 35.367,65.5 31.208,65.7 30.61,65.723 25.603,66.03 26.638,66.03 27.638,66.03 24.694,66.046 28.638,66.046 29.396,66.046 32.557,66.115 33.662,66.115 34.779,66.115 35.857,66.115 31.208,66.268 31.768,66.26 30.61,66.291 36.543,66.403 33.11,66.627 34.189,66.608 35.315,66.627 31.208,66.844 30.61,66.866 31.768,66.892 36.552,67.021 24.685,67.054 29.412,67.063 32.557,67.098 33.662,67.098 34.779,67.098 35.857,67.098 31.208,67.375 30.61,67.397 31.768,67.672 33.076,67.695 34.189,67.695 35.333,67.695 31.208,67.979 30.61,68.002 24.669,68.054 29.412,68.063 32.557,68.335 33.662,68.335 34.779,68.335 35.857,68.335 31.211,68.502 30.613,68.525 24.694,68.94 29.412,68.94 25.565,69.04 26.603,69.04 27.638,69.04 28.638,69.04 30.61,69.054 31.505,69.088 32.084,69.088 32.624,69.088 33.193,69.088 33.768,69.088 34.299,69.088 30.141,69.339 30.61,69.581 31.864,69.729 32.443,69.729 32.983,69.729 30.141,69.87 26.517,70.097 27.058,70.097 27.626,70.097 28.201,70.097 28.732,70.097 32.696,70.293 30.815,70.429 32.086,70.429 30.141,70.445 31.482,70.445 26.53,70.824 27.071,70.824 27.639,70.824 28.214,70.824 28.745,70.824 32.696,70.824 30.141,71.014 31.482,71.084 32.696,71.4 26.517,71.554 27.058,71.554 27.626,71.554 28.201,71.554 28.732,71.554 30.141,71.554 31.505,71.687
SHB: C72.1 J8.1 Q7.1 Q7.2 Q7.3 Q9.5 R69.1 U5.44 | length 64.9
  Top Layer w0.2: Q7.3@15.308,69.493 15.373,69.559 16.108,69.559 16.566,70.017 R69.1@16.566,70.117
  Top Layer w0.25: v1(36.182,28.065) 36.25,28.065 36.55,27.765 U5.44@39.343,27.765
  Top Layer w0.4: R69.1@16.566,70.117 16.566,70.217 16.866,70.517 18.945,70.517 19.002,70.573 v1(21.108,70.573)
  Sig4 w0.2: v1(21.108,70.573) 21.161,70.52 21.433,70.52 23.33,68.624 23.33,63.393 23.596,63.127 25.771,63.127 27.24,61.658 27.24,53.718 23.199,49.677 23.199,42.279 35.544,29.934 35.544,28.706 36.182,28.068 v1(36.182,28.065)
  Bottom Layer w0.2: C72.1@34.888,29.145 35.544,28.489 35.762,28.489 36.182,28.068 v1(36.182,28.065)
  other v1: 12.746,58.935 11.673,59.601 13.461,59.619 10.997,60.265 14.244,60.399 10.398,60.961 14.858,61.039 10.936,61.751 15.695,61.751 11.611,62.427 15.541,62.834 12.364,63.102 21.303,63.191 18.575,63.202 19.297,63.202 19.947,63.202 20.61,63.202 21.899,63.202 17.85,63.253 15.076,63.392 17.194,63.538 12.91,63.777 14.414,63.834 17.85,63.889 22.561,63.889 17.194,64.078 18.463,64.071 19.7,64.071 20.684,64.071 21.921,64.071 13.42,64.359 19.085,64.56 21.28,64.595 20.212,64.613 17.194,64.647 18.463,65.149 19.7,65.149 20.684,65.149 21.921,65.149 17.785,65.197 17.194,65.222 22.561,65.339 19.047,65.714 20.194,65.739 21.28,65.739 14.369,65.753 14.9,65.753 15.476,65.753 16.044,65.753 16.584,65.753 17.194,65.753 17.785,65.828 22.569,65.958 18.463,66.266 19.7,66.266 20.684,66.266 21.921,66.266 17.194,66.357 14.369,66.403 14.9,66.403 15.476,66.403 16.044,66.403 16.584,66.403 17.785,66.608 22.561,66.608 19.047,66.818 20.212,66.818 21.28,66.852 17.197,66.88 18.463,67.371 19.7,67.371 20.684,67.371 21.921,67.371 17.194,67.41 15.027,67.643 15.603,67.643 16.171,67.643 16.711,67.643 17.523,68.024 18.101,68.024 18.641,68.024 19.21,68.024 19.785,68.024 20.316,68.024 20.921,68.024 21.443,68.021 21.973,68.024 22.5,68.024 16.446,68.311 17.523,68.724 18.101,68.724 18.641,68.724 19.21,68.724 19.785,68.724 20.316,68.724 20.921,68.724 21.443,68.721 21.973,68.724 15.025,68.872 15.6,68.872 16.169,68.872 16.709,68.872 17.371,69.264 17.902,69.264 18.478,69.264 19.046,69.264 19.586,69.264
